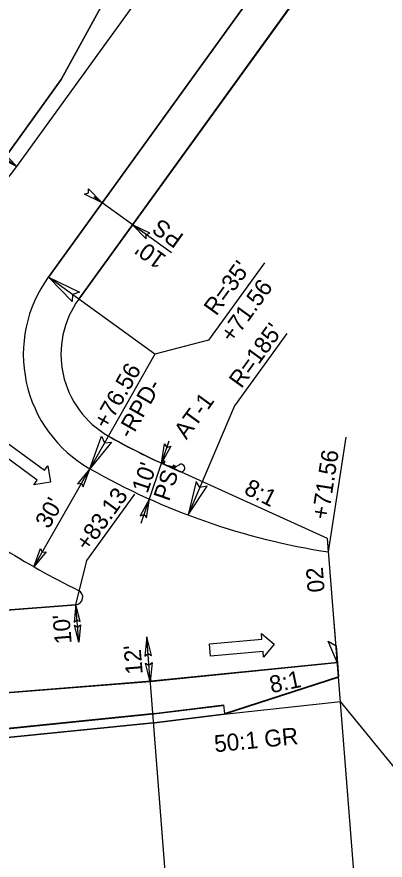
# Model space of a CAD drawing. Extents: x 1183930 to 1185370, y 573068 to 574871.
# Drawn here: x 1184397.2 to 1184495.2, y 573704.9 to 573929 of the extents above; entities that cross this region are included whole.
import ezdxf

# ---------------------------------------------------------------- set-up
doc = ezdxf.new("R2010")
doc.units = 0
for name, color, linetype in [('E_NCDOT_Terrain_Model_Breakline', 7, 'Continuous'), ('E_NCDOT_Terrain_Model_Contour_Minor', 7, 'Continuous'), ('E_NCDOT_Terrain_Model_Points_High', 7, 'Continuous'), ('E_NCDOT_Terrain_Model_Triangles', 7, 'Continuous'), ('E_NCDOT_Vertical_Profile_Ground_Line', 7, 'Continuous'), ('P_NCDOT_Horizontal_Alignment', 7, 'Continuous'), ('P_NCDOT_Horizontal_Alignment_Station_Major_Label', 7, 'Continuous'), ('P_NCDOT_Horizontal_Alignment_Tick_Large', 7, 'Continuous'), ('PC_BEAM', 7, 'Continuous'), ('PC_COLUMN', 7, 'Continuous'), ('PC_OBJECT', 7, 'Continuous'), ('PC_PADFOOTING', 7, 'Continuous'), ('PC_SLAB', 7, 'Continuous'), ('PS_HATCH', 7, 'Continuous')]:
    doc.layers.add(name, color=color, linetype=linetype)

msp = doc.modelspace()

# ---------------------------------------------------------------- linework, layer by layer
for points in [[(1184416.29, 573883.25), (1184419.88, 573879.57), (1184415.23, 573881.83), (1184416.28, 573882.18)], [(1184432.6, 573871.45), (1184427.98, 573873.71), (1184431.58, 573870), (1184431.58, 573871.11)], [(1184438.17, 573814.87), (1184435.71, 573810.36), (1184436.5, 573815.47), (1184437.14, 573814.57)], [(1184414.87, 573804.07), (1184416.62, 573808.9), (1184413.32, 573804.92), (1184414.42, 573805.04)], [(1184431.66, 573795.83), (1184432.47, 573800.9), (1184429.98, 573796.37), (1184431.04, 573796.69)], [(1184405.03, 573786.8), (1184401.77, 573782.83), (1184403.51, 573787.7), (1184403.97, 573786.69)], [(1184414.04, 573768.29), (1184412.9, 573772.77), (1184412.45, 573768.14), (1184413.21, 573768.78)], [(1184414.11, 573767.41), (1184413.69, 573762.8), (1184412.52, 573767.31), (1184413.37, 573766.79)], [(1184433.04, 573759.26), (1184431.77, 573764.23), (1184431.27, 573759.09), (1184432.12, 573759.8)], [(1184433.18, 573757.39), (1184432.71, 573752.27), (1184431.42, 573757.27), (1184432.36, 573756.7)]]:
    msp.add_lwpolyline(points, close=True)
at = {"layer": 'E_NCDOT_Terrain_Model_Breakline'}
msp.add_line((1184350.48, 573767.83), (1184412.9, 573772.77), dxfattribs=at)
for centre, radius, start, end in [((1184508.19, 573969.64), 215, 231.2694, 243.904), ((1184412.74, 573774.77), 2, 274.5263, 63.904)]:
    msp.add_arc(centre, radius, start, end, dxfattribs=at)
at = {"layer": 'E_NCDOT_Terrain_Model_Contour_Minor'}
for p, q in [((1184352.59, 573921.42), (1184397.22, 573889.19)), ((1184433.94, 573839.31), (1184405.59, 573859.83)), ((1184468.99, 573844.78), (1184455.12, 573825.61)), ((1184448.17, 573843.05), (1184433.94, 573839.31)), ((1184433.94, 573839.31), (1184416.62, 573808.9)), ((1184455.12, 573825.61), (1184442.78, 573796.6))]:
    msp.add_line(p, q, dxfattribs=at)
for points in [[(1184390.83, 573895.72), (1184397.22, 573889.19), (1184388.94, 573893.19), (1184390.81, 573893.82)], [(1184411.97, 573853.3), (1184405.59, 573859.83), (1184413.86, 573855.82), (1184411.99, 573855.2)], [(1184422.42, 573815.95), (1184416.62, 573808.9), (1184419.71, 573817.55), (1184420.53, 573815.76)], [(1184444.87, 573805.48), (1184442.78, 573796.6), (1184447.79, 573804.3), (1184445.87, 573803.87)]]:
    msp.add_lwpolyline(points, close=True, dxfattribs=at)
msp.add_lwpolyline([(1184463.07, 573863.58), (1184448.17, 573843.05)], dxfattribs=at)
at = {"layer": 'E_NCDOT_Terrain_Model_Points_High'}
msp.add_line((1184412.9, 573772.77), (1184350.48, 573767.83), dxfattribs=at)
for centre, radius, start, end in [((1184508.19, 573969.64), 215, 231.2694, 243.904), ((1184412.74, 573774.77), 2, 274.5263, 63.904)]:
    msp.add_arc(centre, radius, start, end, dxfattribs=at)
at = {"layer": 'E_NCDOT_Terrain_Model_Triangles'}
for p, q in [((1184433.67, 573743.75), (1184452.03, 573746.01)), ((1184383.64, 573738.69), (1184433.67, 573743.75))]:
    msp.add_line(p, q, dxfattribs=at)
at = {"layer": 'E_NCDOT_Vertical_Profile_Ground_Line'}
for p, q in [((1184413.69, 573853.97), (1184639.53, 574165.99)), ((1184413.69, 573853.97), (1184639.53, 574165.99)), ((1184409.04, 573912.35), (1184434.28, 573958.31)), ((1184409.04, 573912.35), (1184434.28, 573958.31)), ((1184393.98, 573891.54), (1184409.04, 573912.35)), ((1184393.98, 573891.54), (1184409.04, 573912.35)), ((1184479.85, 573790.34), (1184436.1, 573810.18)), ((1184479.85, 573790.34), (1184436.1, 573810.18)), ((1184482.76, 573753.54), (1184452.31, 573743.7)), ((1184452.31, 573743.7), (1184482.76, 573753.54)), ((1184452.31, 573743.7), (1184433.81, 573741.42)), ((1184433.81, 573741.42), (1184452.31, 573743.7)), ((1184433.58, 573741.4), (1184383.84, 573736.36)), ((1184383.84, 573736.36), (1184433.58, 573741.4))]:
    msp.add_line(p, q, dxfattribs=at)
for centre, radius, start, end in [((1184433.94, 573839.31), 25, 144.103, 240.3309), ((1184433.94, 573839.31), 25, 144.103, 240.3309), ((1184508.19, 573969.64), 175, 240.3309, 245.6711), ((1184508.19, 573969.64), 175, 240.3309, 245.6711)]:
    msp.add_arc(centre, radius, start, end, dxfattribs=at)
at = {"layer": 'P_NCDOT_Horizontal_Alignment'}
for p, q in [((1184397.22, 573889.19), (1184673.34, 574270.68)), ((1184405.59, 573859.83), (1184695.92, 574260.95)), ((1184482.76, 573753.54), (1184479.85, 573790.34)), ((1184482.46, 573757.29), (1184432.71, 573752.27)), ((1184482.46, 573757.29), (1184432.71, 573752.27)), ((1184432.71, 573752.27), (1184315.83, 573743.02)), ((1184432.71, 573752.27), (1184376.53, 573747.82)), ((1184432.71, 573752.27), (1184376.53, 573747.82))]:
    msp.add_line(p, q, dxfattribs=at)
for centre, radius, start, end in [((1184352.66, 573921.44), 55, 247.677, 324.103), ((1184433.94, 573839.31), 35, 144.103, 240.3309), ((1184508.19, 573969.64), 185, 240.3309, 261.2742)]:
    msp.add_arc(centre, radius, start, end, dxfattribs=at)
at = {"layer": 'P_NCDOT_Horizontal_Alignment_Station_Major_Label'}
for p, q in [((1184436.04, 573811.1), (1184435.71, 573810.36)), ((1184435.71, 573810.36), (1184436.68, 573810.81)), ((1184435.71, 573810.36), (1184438.93, 573808.9)), ((1184435.71, 573810.36), (1184436.34, 573810.07)), ((1184436.68, 573810.81), (1184436.04, 573811.1)), ((1184436.34, 573810.07), (1184436.04, 573811.1)), ((1184436.34, 573810.07), (1184436.68, 573810.81)), ((1184439.02, 573809.3), (1184437.12, 573809.72)), ((1184438.87, 573809.81), (1184438.54, 573809.08)), ((1184438.54, 573809.08), (1184439.51, 573809.52)), ((1184438.54, 573809.08), (1184439.17, 573808.79)), ((1184439.51, 573809.52), (1184438.87, 573809.81)), ((1184439.17, 573808.79), (1184438.87, 573809.81)), ((1184439.05, 573808.84), (1184438.93, 573808.9)), ((1184438.93, 573808.9), (1184440.5, 573808.19)), ((1184439.17, 573808.79), (1184439.51, 573809.52)), ((1184440.43, 573809.96), (1184439.47, 573809.43))]:
    msp.add_line(p, q, dxfattribs=at)
msp.add_ellipse((1184440.91, 573809.09), major_axis=(0.41, 0.904), ratio=0.995379, start_param=3.141593, end_param=7.214552, dxfattribs=at)
at = {"layer": 'P_NCDOT_Horizontal_Alignment_Tick_Large'}
for p, q in [((1184514.4, 573993.1), (1184413.69, 573853.97)), ((1184452.31, 573743.7), (1184483.28, 573747.01)), ((1184452.31, 573743.7), (1184483.28, 573747.01)), ((1184433.81, 573741.42), (1184452.31, 573743.7)), ((1184433.81, 573741.42), (1184452.31, 573743.7)), ((1184383.84, 573736.36), (1184433.58, 573741.4)), ((1184383.84, 573736.36), (1184433.58, 573741.4))]:
    msp.add_line(p, q, dxfattribs=at)
for centre, radius, start, end in [((1184433.94, 573839.31), 25, 144.103, 240.3309), ((1184508.19, 573969.64), 175, 240.3309, 245.53)]:
    msp.add_arc(centre, radius, start, end, dxfattribs=at)
at = {"layer": 'PC_BEAM'}
for p, q in [((1184393.3, 573816.76), (1184404.59, 573808.48)), ((1184402.63, 573805.82), (1184391.35, 573814.1)), ((1184404.59, 573808.48), (1184405.47, 573809.69)), ((1184405.47, 573809.69), (1184406.18, 573805.32)), ((1184401.75, 573804.61), (1184402.63, 573805.82)), ((1184406.18, 573805.32), (1184401.75, 573804.61)), ((1184462.4, 573763.6), (1184462.27, 573765.1)), ((1184462.27, 573765.1), (1184465.67, 573762.28)), ((1184448.45, 573762.39), (1184462.4, 573763.6)), ((1184448.74, 573759.1), (1184448.45, 573762.39)), ((1184465.67, 573762.28), (1184462.81, 573758.82)), ((1184462.68, 573760.31), (1184448.74, 573759.1)), ((1184462.81, 573758.82), (1184462.68, 573760.31))]:
    msp.add_line(p, q, dxfattribs=at)
at = {"layer": 'PC_COLUMN'}
msp.add_lwpolyline([(1184482.47, 573757.21), (1184480, 573763.04), (1184482.1, 573761.82)], close=True, dxfattribs=at)
at = {"layer": 'PC_OBJECT'}
for p, q in [((1184397.22, 573889.19), (1184480.88, 574004.78)), ((1184505.98, 573998.53), (1184405.59, 573859.83)), ((1184434.39, 573958.5), (1184409.04, 573912.35)), ((1184409.04, 573912.35), (1184393.98, 573891.54)), ((1184479.85, 573790.34), (1184436.1, 573810.18)), ((1184480.13, 573786.79), (1184479.85, 573790.34)), ((1184482.58, 573757.45), (1184432.83, 573752.43)), ((1184482.87, 573753.7), (1184482.58, 573757.45)), ((1184452.43, 573743.85), (1184482.87, 573753.7)), ((1184432.83, 573752.43), (1184376.64, 573747.98)), ((1184433.64, 573743.89), (1184452.14, 573746.17)), ((1184452.14, 573746.17), (1184452.43, 573743.85)), ((1184383.75, 573738.85), (1184433.78, 573743.91)), ((1184433.58, 573741.4), (1184433.81, 573741.42))]:
    msp.add_line(p, q, dxfattribs=at)
msp.add_lwpolyline([(1184413.69, 573853.97), (1184497.26, 573969.42), (1184495.37, 573970.79), (1184514.01, 573996.54)], dxfattribs=at)
for centre, radius, start, end in [((1184433.94, 573839.31), 35, 144.103, 240.3309), ((1184433.94, 573839.31), 25, 144.103, 240.3309), ((1184508.19, 573969.64), 175, 240.3309, 245.6711), ((1184508.19, 573969.64), 185, 240.3309, 261.2742)]:
    msp.add_arc(centre, radius, start, end, dxfattribs=at)
at = {"layer": 'PC_PADFOOTING'}
for p, q in [((1184438.33, 573866.22), (1184417.7, 573881.16)), ((1184430.26, 573794.41), (1184437.74, 573816.33)), ((1184480.13, 573786.79), (1184484.81, 573817.27)), ((1184401.77, 573782.83), (1184416.62, 573808.9)), ((1184415.79, 573784.5), (1184428.58, 573802.17)), ((1184412.9, 573772.77), (1184415.79, 573784.5)), ((1184413.69, 573762.8), (1184412.9, 573772.77)), ((1184432.71, 573752.27), (1184431.77, 573764.23)), ((1184441.21, 573644.93), (1184432.65, 573753.09)), ((1184570.71, 573639.99), (1184483.28, 573747.01))]:
    msp.add_line(p, q, dxfattribs=at)
at = {"layer": 'PS_HATCH'}
msp.add_line((1184498.87, 573549.97), (1184481.6, 573768.18), dxfattribs=at)

# ---------------------------------------------------------------- texts
at = {"layer": 'E_NCDOT_Terrain_Model_Contour_Minor'}
for s, rotation, p in [("R=35'", 54.0376, (1184450.24, 573849.3)), ('+71.56', 54.0376, (1184454.57, 573842.07)), ("R=185'", 54.103, (1184456.92, 573830.02))]:
    msp.add_text(s, height=4.5, rotation=rotation, dxfattribs=at).set_placement(p)
at = {"layer": 'PC_PADFOOTING'}
for s, rotation, p in [('PS', 144.103, (1184441.9, 573870.87)), ("10'", 144.103, (1184437.26, 573865.27)), ('+76.56', 60.3309, (1184421.21, 573819.14)), ('-RPD-', 60.3309, (1184427.53, 573816.6)), ('+71.56', 81.0796, (1184479.98, 573795.2)), ("10'", 71.1464, (1184431.93, 573802.14)), ('PS', 71.1464, (1184437.68, 573800.05)), ('8:1', 333.2632, (1184457.35, 573802.37)), ('+83.13', 54.103, (1184416.08, 573786.71)), ("30'", 60.3309, (1184405.73, 573792.69)), ("10'", 94.5269, (1184411.81, 573762.48)), ("12'", 94.5269, (1184430.7, 573754.39)), ('8:1', 11.6514, (1184464.91, 573749.25)), ('50:1 GR', 5.6304, (1184449.91, 573733.54))]:
    msp.add_text(s, height=4.5, rotation=rotation, dxfattribs=at).set_placement(p)
at = {"layer": 'PC_SLAB'}
msp.add_text('02', height=4.5, rotation=94.5263, dxfattribs=at).set_placement((1184479.09, 573776.21))
at = {"layer": 'PS_HATCH'}
msp.add_text('AT-1', height=4.5, rotation=54.0376, dxfattribs=at).set_placement((1184442.3, 573816.43))

doc.saveas('drawing.dxf')
